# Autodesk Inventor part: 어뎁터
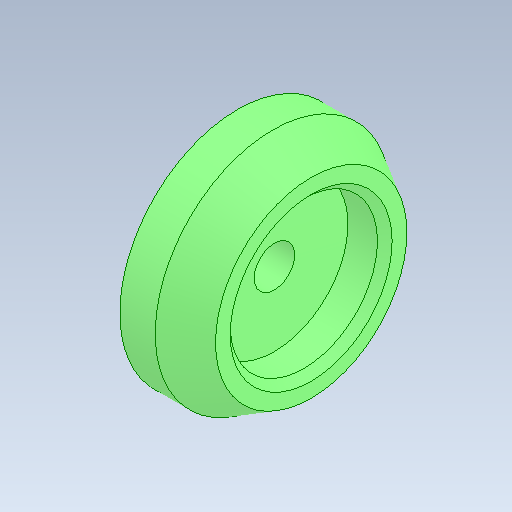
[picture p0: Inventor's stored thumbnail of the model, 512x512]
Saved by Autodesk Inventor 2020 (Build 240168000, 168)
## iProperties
Created: 2024-09
Part Number: 어뎁터
Material: 강철, 탄소
Document SubType Name: Modeling
Designer: oem
Density: 7.85 g/cm^3
Appearance: 기본값
Author: jhkim
Sending System: Autodesk Inventor 2025
Preprocessor: ST-DEVELOPER v20
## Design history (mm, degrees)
feature "솔리드1"
node "솔리드2"
